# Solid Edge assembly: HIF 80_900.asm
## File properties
Title: Zylinder
Author: ahadarics
Template: iso assembly.asm
Last saved by: ahadarics
Revision: 82
Application: Solid Edge
Username: ahadarics
Dokumentum tartalom típus: 1
Document Number: HIF 80/900
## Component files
Kit_2.par
Kit_1.par
Profilrohr 80_900.par
Kolbenstange 80_900.par
Mutter.par
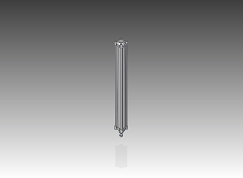
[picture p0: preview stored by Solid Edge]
